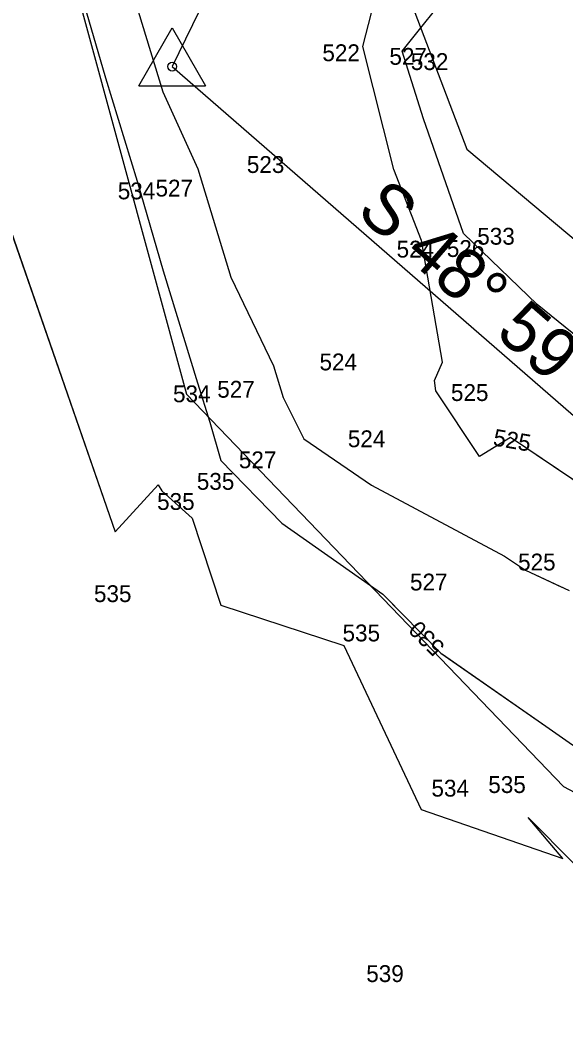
# Model space of a CAD drawing. Extents: x 1787461 to 1970323, y 938412 to 1118748.
# Drawn here: x 1967710 to 1967774.9, y 1117447.9 to 1117568.5 of the extents above; entities that cross this region are included whole.
import ezdxf

# ---------------------------------------------------------------- set-up
doc = ezdxf.new("R2010")
doc.units = 0
for name, color, linetype in [('Default', 7, 'Continuous'), ('RD_EX_DV_Prop', 7, 'Continuous'), ('RD_EX_H2O', 7, 'Continuous'), ('RD_HC_CL', 7, 'Continuous'), ('RD_HC_Data', 7, 'Continuous'), ('RD_SMD_Locator', 7, 'Continuous')]:
    doc.layers.add(name, color=color, linetype=linetype)

msp = doc.modelspace()

# ---------------------------------------------------------------- linework, layer by layer
at = {"layer": 'Default'}
for points in [[(1967771.44, 1117667.74), (1967770.91, 1117666.58), (1967766.29, 1117656.64), (1967763.32, 1117650.45), (1967751.11, 1117634.84), (1967748.24, 1117630.58), (1967737.85, 1117617.66), (1967736.72, 1117615.83), (1967735.76, 1117615.23), (1967728.69, 1117609.8), (1967725.03, 1117596.81), (1967720.87, 1117585.9), (1967718.61, 1117578.34), (1967716.75, 1117573.41), (1967720.15, 1117561.67), (1967723.91, 1117549.41), (1967727.02, 1117538.75), (1967731.11, 1117525.43), (1967732.54, 1117520.76), (1967733.88, 1117516.2), (1967741.13, 1117508.75), (1967753.13, 1117500.33), (1967755.97, 1117497.44)], [(1967771.44, 1117667.74), (1967770.91, 1117666.58), (1967766.29, 1117656.64), (1967763.32, 1117650.45), (1967751.11, 1117634.84), (1967748.24, 1117630.58), (1967737.85, 1117617.66), (1967736.72, 1117615.83), (1967735.76, 1117615.23), (1967728.69, 1117609.8), (1967725.03, 1117596.81), (1967720.87, 1117585.9), (1967718.61, 1117578.34), (1967716.75, 1117573.41), (1967720.15, 1117561.67), (1967723.91, 1117549.41), (1967727.02, 1117538.75), (1967731.11, 1117525.43), (1967732.54, 1117520.76), (1967733.88, 1117516.2), (1967741.13, 1117508.75), (1967753.13, 1117500.33), (1967755.97, 1117497.44)], [(1967771.44, 1117667.74), (1967770.91, 1117666.58), (1967766.29, 1117656.64), (1967763.32, 1117650.45), (1967751.11, 1117634.84), (1967748.24, 1117630.58), (1967737.85, 1117617.66), (1967736.72, 1117615.83), (1967735.76, 1117615.23), (1967728.69, 1117609.8), (1967725.03, 1117596.81), (1967720.87, 1117585.9), (1967718.61, 1117578.34), (1967716.75, 1117573.41), (1967720.15, 1117561.67), (1967723.91, 1117549.41), (1967727.02, 1117538.75), (1967731.11, 1117525.43), (1967732.54, 1117520.76), (1967733.88, 1117516.2), (1967741.13, 1117508.75), (1967753.13, 1117500.33), (1967755.97, 1117497.44)], [(1967771.44, 1117667.74), (1967770.91, 1117666.58), (1967766.29, 1117656.64), (1967763.32, 1117650.45), (1967751.11, 1117634.84), (1967748.24, 1117630.58), (1967737.85, 1117617.66), (1967736.72, 1117615.83), (1967735.76, 1117615.23), (1967728.69, 1117609.8), (1967725.03, 1117596.81), (1967720.87, 1117585.9), (1967718.61, 1117578.34), (1967716.75, 1117573.41), (1967720.15, 1117561.67), (1967723.91, 1117549.41), (1967727.02, 1117538.75), (1967731.11, 1117525.43), (1967732.54, 1117520.76), (1967733.88, 1117516.2), (1967741.13, 1117508.75), (1967753.13, 1117500.33), (1967755.97, 1117497.44)], [(1967771.44, 1117667.74), (1967770.91, 1117666.58), (1967766.29, 1117656.64), (1967763.32, 1117650.45), (1967751.11, 1117634.84), (1967748.24, 1117630.58), (1967737.85, 1117617.66), (1967736.72, 1117615.83), (1967735.76, 1117615.23), (1967728.69, 1117609.8), (1967725.03, 1117596.81), (1967720.87, 1117585.9), (1967718.61, 1117578.34), (1967716.75, 1117573.41), (1967720.15, 1117561.67), (1967723.91, 1117549.41), (1967727.02, 1117538.75), (1967731.11, 1117525.43), (1967732.54, 1117520.76), (1967733.88, 1117516.2), (1967741.13, 1117508.75), (1967753.13, 1117500.33), (1967755.97, 1117497.44)], [(1967771.44, 1117667.74), (1967770.91, 1117666.58), (1967766.29, 1117656.64), (1967763.32, 1117650.45), (1967751.11, 1117634.84), (1967748.24, 1117630.58), (1967737.85, 1117617.66), (1967736.72, 1117615.83), (1967735.76, 1117615.23), (1967728.69, 1117609.8), (1967725.03, 1117596.81), (1967720.87, 1117585.9), (1967718.61, 1117578.34), (1967716.75, 1117573.41), (1967720.15, 1117561.67), (1967723.91, 1117549.41), (1967727.02, 1117538.75), (1967731.11, 1117525.43), (1967732.54, 1117520.76), (1967733.88, 1117516.2), (1967741.13, 1117508.75), (1967753.13, 1117500.33), (1967755.97, 1117497.44)], [(1967750.76, 1117565.39), (1967754.46, 1117579.87)], [(1967750.76, 1117565.39), (1967754.46, 1117579.87)], [(1967750.76, 1117565.39), (1967754.46, 1117579.87)], [(1967750.76, 1117565.39), (1967754.46, 1117579.87)], [(1967750.76, 1117565.39), (1967754.46, 1117579.87)], [(1967750.76, 1117565.39), (1967754.46, 1117579.87)], [(1967750.76, 1117565.39), (1967754.46, 1117579.87)], [(1967722.57, 1117574.41), (1967726.98, 1117560.01), (1967731.12, 1117550.87), (1967735.06, 1117537.99), (1967740.14, 1117527.46), (1967741.29, 1117523.69), (1967743.73, 1117518.78), (1967751.79, 1117513.29), (1967767.61, 1117504.85), (1967770.08, 1117503.2), (1967775.29, 1117500.76)], [(1967722.57, 1117574.41), (1967726.98, 1117560.01), (1967731.12, 1117550.87), (1967735.06, 1117537.99), (1967740.14, 1117527.46), (1967741.29, 1117523.69), (1967743.73, 1117518.78), (1967751.79, 1117513.29), (1967767.61, 1117504.85), (1967770.08, 1117503.2), (1967774.4, 1117501.17)], [(1967722.57, 1117574.41), (1967726.98, 1117560.01), (1967731.12, 1117550.87), (1967735.06, 1117537.99), (1967740.14, 1117527.46), (1967741.29, 1117523.69), (1967743.73, 1117518.78), (1967751.79, 1117513.29), (1967767.61, 1117504.85), (1967770.08, 1117503.2), (1967774.4, 1117501.17)], [(1967722.57, 1117574.41), (1967726.98, 1117560.01), (1967731.12, 1117550.87), (1967735.06, 1117537.99), (1967740.14, 1117527.46), (1967741.29, 1117523.69), (1967743.73, 1117518.78), (1967751.79, 1117513.29), (1967767.61, 1117504.85), (1967770.08, 1117503.2), (1967774.4, 1117501.17)], [(1967722.57, 1117574.41), (1967726.98, 1117560.01), (1967731.12, 1117550.87), (1967735.06, 1117537.99), (1967740.14, 1117527.46), (1967741.29, 1117523.69), (1967743.73, 1117518.78), (1967751.79, 1117513.29), (1967767.61, 1117504.85), (1967770.08, 1117503.2), (1967774.4, 1117501.17)], [(1967722.57, 1117574.41), (1967726.98, 1117560.01), (1967731.12, 1117550.87), (1967735.06, 1117537.99), (1967740.14, 1117527.46), (1967741.29, 1117523.69), (1967743.73, 1117518.78), (1967751.79, 1117513.29), (1967767.61, 1117504.85), (1967770.08, 1117503.2), (1967774.4, 1117501.17)], [(1967722.57, 1117574.41), (1967726.98, 1117560.01), (1967731.12, 1117550.87), (1967735.06, 1117537.99), (1967740.14, 1117527.46), (1967741.29, 1117523.69), (1967743.73, 1117518.78), (1967751.79, 1117513.29), (1967767.61, 1117504.85), (1967770.08, 1117503.2), (1967774.4, 1117501.17)], [(1967716.75, 1117573.41), (1967720.15, 1117561.67), (1967723.91, 1117549.41), (1967727.02, 1117538.75), (1967731.11, 1117525.43), (1967732.54, 1117520.76), (1967733.88, 1117516.2), (1967741.13, 1117508.75), (1967753.13, 1117500.33), (1967760.01, 1117493.34), (1967772.53, 1117484.63), (1967775.68, 1117482.44)], [(1967864.09, 1117491.4), (1967860.39, 1117488.79), (1967857.14, 1117486.78), (1967853.13, 1117483.68), (1967853.29, 1117484.04), (1967852.82, 1117483.54), (1967852.36, 1117483.18), (1967846.09, 1117488.43), (1967845.27, 1117490.67), (1967846.19, 1117494.55), (1967828.68, 1117502.13), (1967821.49, 1117503.37), (1967805.34, 1117509.98), (1967800.65, 1117512.37), (1967795, 1117514.63), (1967789.01, 1117520.57), (1967781.48, 1117526.67), (1967771.5, 1117534.74), (1967762.73, 1117543.19), (1967757.96, 1117556.81), (1967755.44, 1117564.85), (1967761.67, 1117572.63)], [(1967864.09, 1117491.4), (1967860.39, 1117488.79), (1967857.14, 1117486.78), (1967853.13, 1117483.68), (1967853.29, 1117484.04), (1967852.82, 1117483.54), (1967852.36, 1117483.18), (1967846.09, 1117488.43), (1967845.27, 1117490.67), (1967846.19, 1117494.55), (1967828.68, 1117502.13), (1967821.49, 1117503.37), (1967805.34, 1117509.98), (1967800.65, 1117512.37), (1967795, 1117514.63), (1967789.01, 1117520.57), (1967781.48, 1117526.67), (1967771.5, 1117534.74), (1967762.73, 1117543.19), (1967757.96, 1117556.81), (1967755.44, 1117564.85), (1967761.67, 1117572.63)], [(1967864.09, 1117491.4), (1967860.39, 1117488.79), (1967857.14, 1117486.78), (1967853.13, 1117483.68), (1967853.29, 1117484.04), (1967852.82, 1117483.54), (1967852.36, 1117483.18), (1967846.09, 1117488.43), (1967845.27, 1117490.67), (1967846.19, 1117494.55), (1967828.68, 1117502.13), (1967821.49, 1117503.37), (1967805.34, 1117509.98), (1967800.65, 1117512.37), (1967795, 1117514.63), (1967789.01, 1117520.57), (1967781.48, 1117526.67), (1967771.5, 1117534.74), (1967762.73, 1117543.19), (1967757.96, 1117556.81), (1967755.44, 1117564.85), (1967761.67, 1117572.63)], [(1967864.09, 1117491.4), (1967860.39, 1117488.79), (1967857.14, 1117486.78), (1967853.13, 1117483.68), (1967853.29, 1117484.04), (1967852.82, 1117483.54), (1967852.36, 1117483.18), (1967846.09, 1117488.43), (1967845.27, 1117490.67), (1967846.19, 1117494.55), (1967828.68, 1117502.13), (1967821.49, 1117503.37), (1967805.34, 1117509.98), (1967800.65, 1117512.37), (1967795, 1117514.63), (1967789.01, 1117520.57), (1967781.48, 1117526.67), (1967771.5, 1117534.74), (1967762.73, 1117543.19), (1967757.96, 1117556.81), (1967755.44, 1117564.85), (1967761.67, 1117572.63)], [(1967864.09, 1117491.4), (1967860.39, 1117488.79), (1967857.14, 1117486.78), (1967853.13, 1117483.68), (1967853.29, 1117484.04), (1967852.82, 1117483.54), (1967852.36, 1117483.18), (1967846.09, 1117488.43), (1967845.27, 1117490.67), (1967846.19, 1117494.55), (1967828.68, 1117502.13), (1967821.49, 1117503.37), (1967805.34, 1117509.98), (1967800.65, 1117512.37), (1967795, 1117514.63), (1967789.01, 1117520.57), (1967781.48, 1117526.67), (1967771.5, 1117534.74), (1967762.73, 1117543.19), (1967757.96, 1117556.81), (1967755.44, 1117564.85), (1967761.67, 1117572.63)], [(1967864.09, 1117491.4), (1967860.39, 1117488.79), (1967857.14, 1117486.78), (1967853.13, 1117483.68), (1967853.29, 1117484.04), (1967852.82, 1117483.54), (1967852.36, 1117483.18), (1967846.09, 1117488.43), (1967845.27, 1117490.67), (1967846.19, 1117494.55), (1967828.68, 1117502.13), (1967821.49, 1117503.37), (1967805.34, 1117509.98), (1967800.65, 1117512.37), (1967795, 1117514.63), (1967789.01, 1117520.57), (1967781.48, 1117526.67), (1967771.5, 1117534.74), (1967762.73, 1117543.19), (1967757.96, 1117556.81), (1967755.44, 1117564.85), (1967761.67, 1117572.63)], [(1967864.09, 1117491.4), (1967860.39, 1117488.79), (1967857.14, 1117486.78), (1967853.13, 1117483.68), (1967853.29, 1117484.04), (1967852.82, 1117483.54), (1967852.36, 1117483.18), (1967846.09, 1117488.43), (1967845.27, 1117490.67), (1967846.19, 1117494.55), (1967828.68, 1117502.13), (1967821.49, 1117503.37), (1967805.34, 1117509.98), (1967800.65, 1117512.37), (1967795, 1117514.63), (1967789.01, 1117520.57), (1967781.48, 1117526.67), (1967771.5, 1117534.74), (1967762.73, 1117543.19), (1967757.96, 1117556.81), (1967755.44, 1117564.85), (1967761.67, 1117572.63)], [(1967837.86, 1117489.36), (1967832.47, 1117491.15), (1967825.83, 1117496.16), (1967806.17, 1117501.4), (1967804.28, 1117501.23), (1967799.24, 1117502.7), (1967788.4, 1117503.91), (1967781.65, 1117508.96), (1967779.72, 1117511.26), (1967768.31, 1117518.95), (1967764.64, 1117516.68), (1967759.43, 1117524.47), (1967759.27, 1117525.73), (1967760.24, 1117527.88), (1967757.73, 1117542.36), (1967754.45, 1117550.79), (1967750.76, 1117565.39)], [(1967766.35, 1117517.74), (1967764.64, 1117516.68), (1967759.43, 1117524.47), (1967759.27, 1117525.73), (1967760.24, 1117527.88), (1967757.73, 1117542.36), (1967754.45, 1117550.79), (1967750.76, 1117565.39)], [(1967766.35, 1117517.74), (1967764.64, 1117516.68), (1967759.43, 1117524.47), (1967759.27, 1117525.73), (1967760.24, 1117527.88), (1967757.73, 1117542.36), (1967754.45, 1117550.79), (1967750.76, 1117565.39)], [(1967766.35, 1117517.74), (1967764.64, 1117516.68), (1967759.43, 1117524.47), (1967759.27, 1117525.73), (1967760.24, 1117527.88), (1967757.73, 1117542.36), (1967754.45, 1117550.79), (1967750.76, 1117565.39)], [(1967766.35, 1117517.74), (1967764.64, 1117516.68), (1967759.43, 1117524.47), (1967759.27, 1117525.73), (1967760.24, 1117527.88), (1967757.73, 1117542.36), (1967754.45, 1117550.79), (1967750.76, 1117565.39)], [(1967766.35, 1117517.74), (1967764.64, 1117516.68), (1967759.43, 1117524.47), (1967759.27, 1117525.73), (1967760.24, 1117527.88), (1967757.73, 1117542.36), (1967754.45, 1117550.79), (1967750.76, 1117565.39)], [(1967766.35, 1117517.74), (1967764.64, 1117516.68), (1967759.43, 1117524.47), (1967759.27, 1117525.73), (1967760.24, 1117527.88), (1967757.73, 1117542.36), (1967754.45, 1117550.79), (1967750.76, 1117565.39)], [(1967703.15, 1117559.88), (1967721.29, 1117507.74), (1967726.43, 1117513.31), (1967726.84, 1117512.62), (1967730.47, 1117509.37), (1967733.85, 1117499.01), (1967748.51, 1117494.25), (1967757.67, 1117474.76), (1967774.54, 1117468.91), (1967770.4, 1117473.79), (1967775.91, 1117468.26), (1967776.03, 1117468.19), (1967777.26, 1117467.38), (1967791.69, 1117452.17), (1967799.51, 1117440.56), (1967803.01, 1117436.4), (1967803.55, 1117436.04), (1967803.99, 1117435.25), (1967807.61, 1117433.26)], [(1967707.45, 1117547.54), (1967721.29, 1117507.74), (1967726.43, 1117513.31), (1967726.84, 1117512.62), (1967730.47, 1117509.37), (1967733.85, 1117499.01), (1967748.51, 1117494.25), (1967757.67, 1117474.76), (1967774.54, 1117468.91), (1967770.4, 1117473.79), (1967775.91, 1117468.26), (1967776.03, 1117468.19), (1967777.26, 1117467.38), (1967791.69, 1117452.17), (1967799.51, 1117440.56), (1967803.01, 1117436.4), (1967803.55, 1117436.04), (1967803.99, 1117435.25), (1967807.61, 1117433.26)], [(1967707.45, 1117547.54), (1967721.29, 1117507.74), (1967726.43, 1117513.31), (1967726.84, 1117512.62), (1967730.47, 1117509.37), (1967733.85, 1117499.01), (1967748.51, 1117494.25), (1967757.67, 1117474.76), (1967774.54, 1117468.91), (1967770.4, 1117473.79), (1967775.91, 1117468.26), (1967776.03, 1117468.19), (1967777.26, 1117467.38), (1967791.69, 1117452.17), (1967799.51, 1117440.56), (1967803.01, 1117436.4), (1967803.55, 1117436.04), (1967803.99, 1117435.25), (1967807.61, 1117433.26)], [(1967707.45, 1117547.54), (1967721.29, 1117507.74), (1967726.43, 1117513.31), (1967726.84, 1117512.62), (1967730.47, 1117509.37), (1967733.85, 1117499.01), (1967748.51, 1117494.25), (1967757.67, 1117474.76), (1967774.54, 1117468.91), (1967770.4, 1117473.79), (1967775.91, 1117468.26), (1967776.03, 1117468.19), (1967777.26, 1117467.38), (1967791.69, 1117452.17), (1967799.51, 1117440.56), (1967803.01, 1117436.4), (1967803.55, 1117436.04), (1967803.99, 1117435.25), (1967807.61, 1117433.26)], [(1967707.45, 1117547.54), (1967721.29, 1117507.74), (1967726.43, 1117513.31), (1967726.84, 1117512.62), (1967730.47, 1117509.37), (1967733.85, 1117499.01), (1967748.51, 1117494.25), (1967757.67, 1117474.76), (1967774.54, 1117468.91), (1967770.4, 1117473.79), (1967775.91, 1117468.26), (1967776.03, 1117468.19), (1967777.26, 1117467.38), (1967791.69, 1117452.17), (1967799.51, 1117440.56), (1967803.01, 1117436.4), (1967803.55, 1117436.04), (1967803.99, 1117435.25), (1967807.61, 1117433.26)], [(1967707.45, 1117547.54), (1967721.29, 1117507.74), (1967726.43, 1117513.31), (1967726.84, 1117512.62), (1967730.47, 1117509.37), (1967733.85, 1117499.01), (1967748.51, 1117494.25), (1967757.67, 1117474.76), (1967774.54, 1117468.91), (1967770.4, 1117473.79), (1967775.91, 1117468.26), (1967776.03, 1117468.19), (1967777.26, 1117467.38), (1967791.69, 1117452.17), (1967799.51, 1117440.56), (1967803.01, 1117436.4), (1967803.55, 1117436.04), (1967803.99, 1117435.25), (1967807.61, 1117433.26)], [(1967707.45, 1117547.54), (1967721.29, 1117507.74), (1967726.43, 1117513.31), (1967726.84, 1117512.62), (1967730.47, 1117509.37), (1967733.85, 1117499.01), (1967748.51, 1117494.25), (1967757.67, 1117474.76), (1967774.54, 1117468.91), (1967770.4, 1117473.79), (1967775.91, 1117468.26), (1967776.03, 1117468.19), (1967777.26, 1117467.38), (1967791.69, 1117452.17), (1967799.51, 1117440.56), (1967803.01, 1117436.4), (1967803.55, 1117436.04), (1967803.99, 1117435.25), (1967807.61, 1117433.26)], [(1967837.86, 1117489.36), (1967832.47, 1117491.15), (1967825.83, 1117496.16), (1967806.17, 1117501.4), (1967804.28, 1117501.23), (1967799.24, 1117502.7), (1967788.4, 1117503.91), (1967781.65, 1117508.96), (1967779.72, 1117511.26), (1967771.37, 1117516.88)], [(1967837.86, 1117489.36), (1967832.47, 1117491.15), (1967825.83, 1117496.16), (1967806.17, 1117501.4), (1967804.28, 1117501.23), (1967799.24, 1117502.7), (1967788.4, 1117503.91), (1967781.65, 1117508.96), (1967779.72, 1117511.26), (1967771.37, 1117516.88)], [(1967837.86, 1117489.36), (1967832.47, 1117491.15), (1967825.83, 1117496.16), (1967806.17, 1117501.4), (1967804.28, 1117501.23), (1967799.24, 1117502.7), (1967788.4, 1117503.91), (1967781.65, 1117508.96), (1967779.72, 1117511.26), (1967771.37, 1117516.88)], [(1967837.86, 1117489.36), (1967832.47, 1117491.15), (1967825.83, 1117496.16), (1967806.17, 1117501.4), (1967804.28, 1117501.23), (1967799.24, 1117502.7), (1967788.4, 1117503.91), (1967781.65, 1117508.96), (1967779.72, 1117511.26), (1967771.37, 1117516.88)], [(1967837.86, 1117489.36), (1967832.47, 1117491.15), (1967825.83, 1117496.16), (1967806.17, 1117501.4), (1967804.28, 1117501.23), (1967799.24, 1117502.7), (1967788.4, 1117503.91), (1967781.65, 1117508.96), (1967779.72, 1117511.26), (1967771.37, 1117516.88)], [(1967837.86, 1117489.36), (1967832.47, 1117491.15), (1967825.83, 1117496.16), (1967806.17, 1117501.4), (1967804.28, 1117501.23), (1967799.24, 1117502.7), (1967788.4, 1117503.91), (1967781.65, 1117508.96), (1967779.72, 1117511.26), (1967771.37, 1117516.88)], [(1967760.21, 1117493.2), (1967772.53, 1117484.63), (1967775.68, 1117482.44), (1967779.55, 1117478.56), (1967788.15, 1117473.67), (1967796.17, 1117468.34), (1967802.58, 1117463.41), (1967815.73, 1117459.23), (1967820.53, 1117455.96), (1967821.67, 1117455.55), (1967821.73, 1117455.57), (1967821.73, 1117455.32), (1967823.12, 1117455.95), (1967821.79, 1117451.31), (1967823.86, 1117452.27), (1967825.53, 1117452.87), (1967825.06, 1117450.6), (1967864.09, 1117491.4)], [(1967760.21, 1117493.2), (1967772.53, 1117484.63), (1967775.68, 1117482.44), (1967779.55, 1117478.56), (1967788.15, 1117473.67), (1967796.17, 1117468.34), (1967802.58, 1117463.41), (1967815.73, 1117459.23), (1967820.53, 1117455.96), (1967821.67, 1117455.55), (1967821.73, 1117455.57), (1967821.73, 1117455.32), (1967823.12, 1117455.95), (1967821.79, 1117451.31), (1967823.86, 1117452.27), (1967825.53, 1117452.87), (1967825.06, 1117450.6), (1967864.09, 1117491.4)], [(1967760.21, 1117493.2), (1967772.53, 1117484.63), (1967775.68, 1117482.44), (1967779.55, 1117478.56), (1967788.15, 1117473.67), (1967796.17, 1117468.34), (1967802.58, 1117463.41), (1967815.73, 1117459.23), (1967820.53, 1117455.96), (1967821.67, 1117455.55), (1967821.73, 1117455.57), (1967821.73, 1117455.32), (1967823.12, 1117455.95), (1967821.79, 1117451.31), (1967823.86, 1117452.27), (1967825.53, 1117452.87), (1967825.06, 1117450.6), (1967864.09, 1117491.4)], [(1967760.21, 1117493.2), (1967772.53, 1117484.63), (1967775.68, 1117482.44), (1967779.55, 1117478.56), (1967788.15, 1117473.67), (1967796.17, 1117468.34), (1967802.58, 1117463.41), (1967815.73, 1117459.23), (1967820.53, 1117455.96), (1967821.67, 1117455.55), (1967821.73, 1117455.57), (1967821.73, 1117455.32), (1967823.12, 1117455.95), (1967821.79, 1117451.31), (1967823.86, 1117452.27), (1967825.53, 1117452.87), (1967825.06, 1117450.6), (1967864.09, 1117491.4)], [(1967760.21, 1117493.2), (1967772.53, 1117484.63), (1967775.68, 1117482.44), (1967779.55, 1117478.56), (1967788.15, 1117473.67), (1967796.17, 1117468.34), (1967802.58, 1117463.41), (1967815.73, 1117459.23), (1967820.53, 1117455.96), (1967821.67, 1117455.55), (1967821.73, 1117455.57), (1967821.73, 1117455.32), (1967823.12, 1117455.95), (1967821.79, 1117451.31), (1967823.86, 1117452.27), (1967825.53, 1117452.87), (1967825.06, 1117450.6), (1967864.09, 1117491.4)], [(1967760.21, 1117493.2), (1967772.53, 1117484.63), (1967775.68, 1117482.44), (1967779.55, 1117478.56), (1967788.15, 1117473.67), (1967796.17, 1117468.34), (1967802.58, 1117463.41), (1967815.73, 1117459.23), (1967820.53, 1117455.96), (1967821.67, 1117455.55), (1967821.73, 1117455.57), (1967821.73, 1117455.32), (1967823.12, 1117455.95), (1967821.79, 1117451.31), (1967823.86, 1117452.27), (1967825.53, 1117452.87), (1967825.06, 1117450.6), (1967864.09, 1117491.4)]]:
    msp.add_lwpolyline(points, dxfattribs=at)
at = {"layer": 'RD_EX_DV_Prop'}
for p, q in [((1967848.59, 1117809.96), (1967728.08, 1117563.01)), ((1967728.08, 1117563.01), (1967829.57, 1117474.78))]:
    msp.add_line(p, q, dxfattribs=at)
at = {"layer": 'RD_EX_H2O'}
for points in [[(1967793.07, 1117884.81), (1967795.4, 1117862.79), (1967808.44, 1117844.76), (1967827.6, 1117817.64), (1967803.85, 1117763.92), (1967785.1, 1117717.4), (1967778.96, 1117698.7), (1967761.45, 1117660.55), (1967735.16, 1117625.66), (1967726.1, 1117620.57), (1967713.81, 1117582.71), (1967729.78, 1117524.09), (1967774.63, 1117477.47), (1967792.06, 1117468.24), (1967815.16, 1117463.54)], [(1967872.32, 1117822.66), (1967872.31, 1117820.09), (1967867.75, 1117800.84), (1967855.06, 1117765.41), (1967833.55, 1117731.08), (1967814.13, 1117687.88), (1967798.73, 1117637.75), (1967777.02, 1117596.99), (1967770.1, 1117591.47), (1967755.23, 1117573.96), (1967763.13, 1117553.21), (1967794.74, 1117526.69), (1967804.69, 1117522.56), (1967827.72, 1117512.92)]]:
    msp.add_lwpolyline(points, dxfattribs=at)
at = {"layer": 'RD_HC_CL'}
for p, q in [((1967848.59, 1117809.96), (1967728.08, 1117563.01)), ((1967728.08, 1117563.01), (1967829.57, 1117474.78))]:
    msp.add_line(p, q, dxfattribs=at)
at = {"layer": 'RD_HC_Data'}
for p, q in [((1967724.11, 1117560.72), (1967728.08, 1117567.6)), ((1967728.08, 1117567.6), (1967732.05, 1117560.72)), ((1967724.11, 1117560.72), (1967732.05, 1117560.72))]:
    msp.add_line(p, q, dxfattribs=at)
msp.add_circle((1967728.08, 1117563.01), 0.529, dxfattribs=at)
at = {"layer": 'RD_SMD_Locator'}
msp.add_circle((1967728.08, 1117563.01), 0.001, dxfattribs=at)

# ---------------------------------------------------------------- texts
at = {"layer": 'Default'}
for s, p in [('522', (1967745.94, 1117563.65)), ('527', (1967753.91, 1117563.22)), ('532', (1967756.46, 1117562.6)), ('523', (1967736.96, 1117550.37)), ('534', (1967721.61, 1117547.24)), ('527', (1967726.1, 1117547.57)), ('533', (1967764.36, 1117541.85)), ('524', (1967754.77, 1117540.32)), ('526', (1967760.74, 1117540.39)), ('524', (1967745.6, 1117526.92)), ('534', (1967728.18, 1117523.13)), ('527', (1967733.44, 1117523.67)), ('525', (1967761.23, 1117523.28)), ('524', (1967748.97, 1117517.79)), ('527', (1967736.01, 1117515.29)), ('535', (1967731.01, 1117512.73)), ('535', (1967726.29, 1117510.34)), ('525', (1967769.21, 1117503.15)), ('527', (1967756.36, 1117500.77)), ('535', (1967718.78, 1117499.39)), ('535', (1967748.34, 1117494.72)), ('534', (1967758.91, 1117476.28)), ('535', (1967765.67, 1117476.71)), ('539', (1967751.16, 1117454.25))]:
    msp.add_text(s, height=2, dxfattribs=at).set_placement(p)
for s, rotation, p in [('525', 350.3459, (1967766.15, 1117518.01)), ('525', 350.3459, (1967766.15, 1117518.01)), ('525', 350.3459, (1967766.15, 1117518.01)), ('525', 350.3459, (1967766.15, 1117518.01)), ('525', 350.3459, (1967766.15, 1117518.01)), ('525', 350.3459, (1967766.15, 1117518.01)), ('530', 134.9627, (1967760.61, 1117494.19)), ('530', 134.9627, (1967760.61, 1117494.19)), ('530', 134.9627, (1967760.61, 1117494.19)), ('530', 134.9627, (1967760.61, 1117494.19)), ('530', 134.9627, (1967760.61, 1117494.19)), ('530', 134.9627, (1967760.61, 1117494.19))]:
    msp.add_text(s, height=2, rotation=rotation, dxfattribs=at).set_placement(p)
at = {"layer": 'RD_HC_Data'}
msp.add_text('S 48%%d 59\' 58" E', height=6, rotation=318.9993, dxfattribs=at).set_placement((1967749.8, 1117545.54))

doc.saveas('drawing.dxf')
